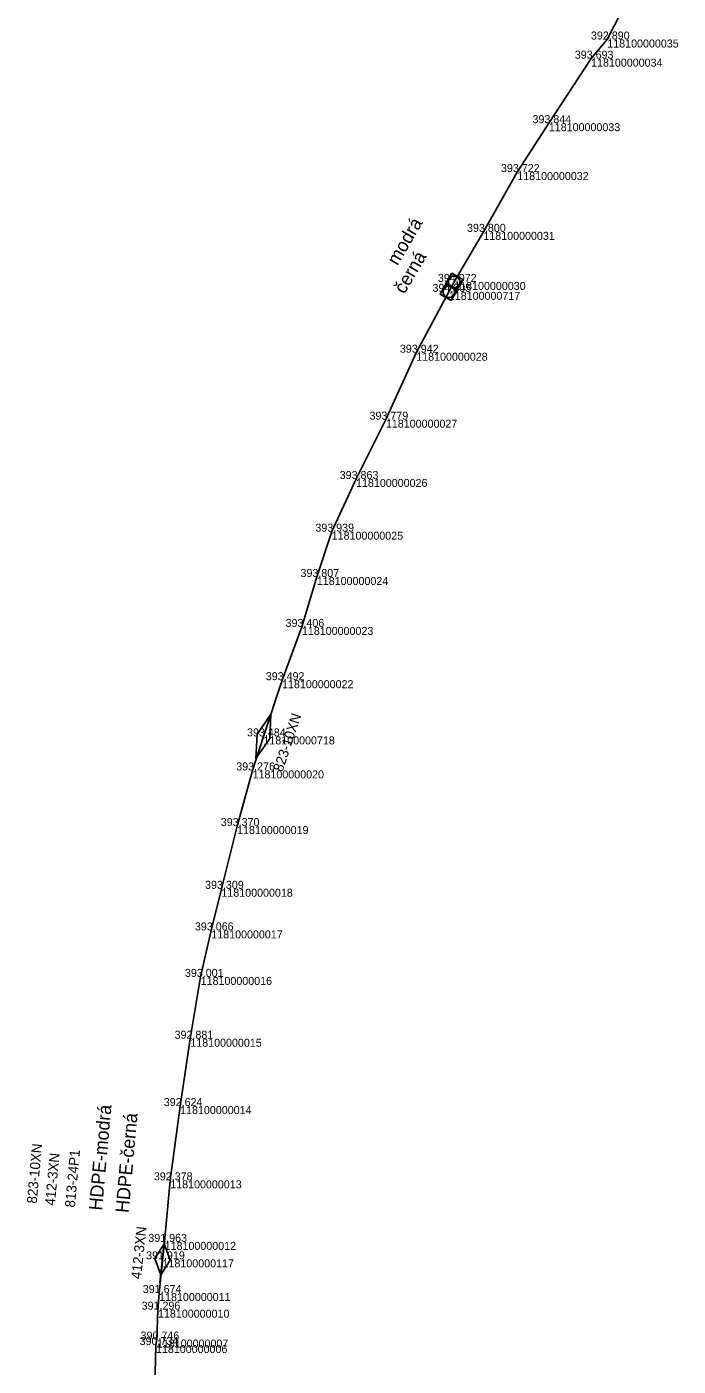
# Model space of a CAD drawing. Extents: x -724084 to -720954, y -948423 to -945131.
# Drawn here: x -721963.8 to -721866.1, y -947400.9 to -947200 of the extents above; entities that cross this region are included whole.
import ezdxf

# ---------------------------------------------------------------- set-up
doc = ezdxf.new("R2010")
doc.units = 0
for name, color, linetype in [('Vrstva 28', 7, 'Continuous'), ('Vrstva 31', 7, 'Continuous'), ('Vrstva 33', 7, 'Continuous'), ('Vrstva 60', 7, 'Continuous'), ('Vrstva 61', 7, 'Continuous')]:
    doc.layers.add(name, color=color, linetype=linetype)

msp = doc.modelspace()

# ---------------------------------------------------------------- linework, layer by layer
at = {"layer": 'Vrstva 28'}
for p, q in [((-721943.82, -947388.32), (-721943.07, -947381.38)), ((-721944.6, -947384.73), (-721943.19, -947382.54)), ((-721943.19, -947382.54), (-721942.28, -947384.98)), ((-721943.69, -947387.17), (-721944.6, -947384.73)), ((-721942.28, -947384.98), (-721943.69, -947387.17))]:
    msp.add_line(p, q, dxfattribs=at)
msp.add_lwpolyline([(-721944.57, -947404.06), (-721944.42, -947397.7), (-721944.28, -947396.88), (-721944.12, -947392.4), (-721943.95, -947389.9), (-721943.12, -947382.23), (-721942.28, -947373), (-721940.8, -947361.86), (-721939.27, -947351.76), (-721937.72, -947342.48), (-721936.12, -947335.51), (-721934.61, -947329.27), (-721932.25, -947319.86), (-721929.93, -947311.51), (-721928.31, -947306.41), (-721925.51, -947297.98), (-721922.53, -947289.99), (-721920.29, -947282.5), (-721918.06, -947275.7), (-721914.41, -947267.8), (-721909.93, -947258.9), (-721905.38, -947248.86), (-721900.49, -947239.73), (-721899.68, -947238.24), (-721895.31, -947230.73), (-721890.22, -947221.76), (-721885.49, -947214.43), (-721879.15, -947204.75), (-721876.72, -947201.88), (-721874.78, -947198.06)], dxfattribs=at)
at = {"layer": 'Vrstva 31'}
for points in [[(-721944.57, -947404.06), (-721944.42, -947397.7), (-721944.28, -947396.88), (-721944.12, -947392.4), (-721943.95, -947389.9), (-721943.12, -947382.23), (-721942.28, -947373), (-721940.8, -947361.86), (-721939.27, -947351.76), (-721937.72, -947342.48), (-721936.12, -947335.51), (-721934.61, -947329.27), (-721932.25, -947319.86), (-721929.93, -947311.51), (-721928.31, -947306.41), (-721925.51, -947297.98), (-721922.53, -947289.99), (-721920.29, -947282.5), (-721918.06, -947275.7), (-721914.41, -947267.8), (-721909.93, -947258.9), (-721905.38, -947248.86), (-721900.49, -947239.73), (-721899.68, -947238.24), (-721895.31, -947230.73), (-721890.22, -947221.76), (-721885.49, -947214.43), (-721879.15, -947204.75), (-721876.72, -947201.88), (-721874.78, -947198.06)], [(-721929.42, -947309.73), (-721929.26, -947306.1), (-721927.21, -947303.09), (-721927.36, -947306.73), (-721929.42, -947309.73)]]:
    msp.add_lwpolyline(points, dxfattribs=at)
at = {"layer": 'Vrstva 33'}
msp.add_lwpolyline([(-721944.57, -947404.06), (-721944.42, -947397.7), (-721944.28, -947396.88), (-721944.12, -947392.4), (-721943.95, -947389.9), (-721943.12, -947382.23), (-721942.28, -947373), (-721940.8, -947361.86), (-721939.27, -947351.76), (-721937.72, -947342.48), (-721936.12, -947335.51), (-721934.61, -947329.27), (-721932.25, -947319.86), (-721929.93, -947311.51), (-721928.31, -947306.41), (-721925.51, -947297.98), (-721922.53, -947289.99), (-721920.29, -947282.5), (-721918.06, -947275.7), (-721914.41, -947267.8), (-721909.93, -947258.9), (-721905.38, -947248.86), (-721900.49, -947239.73), (-721899.68, -947238.24), (-721895.31, -947230.73), (-721890.22, -947221.76), (-721885.49, -947214.43), (-721879.15, -947204.75), (-721876.72, -947201.88), (-721874.78, -947198.06)], dxfattribs=at)
for points in [[(-721899.33, -947239.55), (-721898.37, -947237.89), (-721900.03, -947236.93), (-721900.99, -947238.59)], [(-721900.14, -947241.05), (-721899.18, -947239.39), (-721900.83, -947238.42), (-721901.8, -947240.08)]]:
    msp.add_lwpolyline(points, close=True, dxfattribs=at)
for centre in [(-721900.49, -947239.73), (-721899.68, -947238.24)]:
    msp.add_circle(centre, 0.864, dxfattribs=at)
at = {"layer": 'Vrstva 60'}
for p, q in [((-721876.72, -947201.88), (-721876.72, -947201.88)), ((-721879.15, -947204.75), (-721879.15, -947204.75)), ((-721885.49, -947214.43), (-721885.49, -947214.43)), ((-721890.22, -947221.76), (-721890.22, -947221.76)), ((-721895.31, -947230.73), (-721895.31, -947230.73)), ((-721899.68, -947238.24), (-721899.68, -947238.24)), ((-721900.49, -947239.73), (-721900.49, -947239.73)), ((-721905.38, -947248.86), (-721905.38, -947248.86)), ((-721909.93, -947258.9), (-721909.93, -947258.9)), ((-721914.41, -947267.8), (-721914.41, -947267.8)), ((-721918.06, -947275.7), (-721918.06, -947275.7)), ((-721920.29, -947282.5), (-721920.29, -947282.5)), ((-721922.53, -947289.99), (-721922.53, -947289.99)), ((-721925.51, -947297.98), (-721925.51, -947297.98)), ((-721928.31, -947306.41), (-721928.31, -947306.41)), ((-721929.93, -947311.51), (-721929.93, -947311.51)), ((-721932.25, -947319.86), (-721932.25, -947319.86)), ((-721934.61, -947329.27), (-721934.61, -947329.27)), ((-721936.12, -947335.51), (-721936.12, -947335.51)), ((-721937.72, -947342.48), (-721937.72, -947342.48)), ((-721939.27, -947351.76), (-721939.27, -947351.76)), ((-721940.8, -947361.86), (-721940.8, -947361.86)), ((-721942.28, -947373), (-721942.28, -947373)), ((-721943.12, -947382.23), (-721943.12, -947382.23)), ((-721943.44, -947384.85), (-721943.44, -947384.85)), ((-721943.95, -947389.9), (-721943.95, -947389.9)), ((-721944.12, -947392.4), (-721944.12, -947392.4)), ((-721944.28, -947396.88), (-721944.28, -947396.88)), ((-721944.42, -947397.7), (-721944.42, -947397.7))]:
    msp.add_line(p, q, dxfattribs=at)

# ---------------------------------------------------------------- texts
at = {"layer": 'Vrstva 28'}
for s, rotation, p in [('412-3XN', 84.8218, (-721959.59, -947376.84)), ('813-24P1', 84.8218, (-721956.6, -947377.12)), ('412-3XN', 83.8139, (-721946.68, -947387.87))]:
    msp.add_text(s, height=1.5, rotation=rotation, dxfattribs=at).set_placement(p)
at = {"layer": 'Vrstva 31'}
for rotation, p in [(71.5854, (-721925.46, -947311.83)), (84.8218, (-721962.32, -947376.54))]:
    msp.add_text('823-10XN', height=1.5, rotation=rotation, dxfattribs=at).set_placement(p)
at = {"layer": 'Vrstva 33'}
for s, rotation, p in [('modrá', 59.7849, (-721908.18, -947235.9)), ('černá', 59.7849, (-721907.14, -947240.16)), ('HDPE-modrá', 84.8218, (-721952.52, -947377.58)), ('HDPE-černá', 84.8218, (-721948.53, -947377.94))]:
    msp.add_text(s, height=2, rotation=rotation, dxfattribs=at).set_placement(p)
at = {"layer": 'Vrstva 60'}
for s, p in [('118100000035', (-721876.72, -947203.08)), ('118100000034', (-721879.15, -947205.95)), ('118100000033', (-721885.49, -947215.63)), ('118100000032', (-721890.22, -947222.96)), ('118100000031', (-721895.31, -947231.93)), ('118100000030', (-721899.68, -947239.44)), ('118100000717', (-721900.49, -947240.93)), ('118100000028', (-721905.38, -947250.06)), ('118100000027', (-721909.93, -947260.1)), ('118100000026', (-721914.41, -947268.99)), ('118100000025', (-721918.06, -947276.9)), ('118100000024', (-721920.29, -947283.7)), ('118100000023', (-721922.53, -947291.19)), ('118100000022', (-721925.51, -947299.18)), ('118100000718', (-721928.31, -947307.61)), ('118100000020', (-721929.93, -947312.71)), ('118100000019', (-721932.25, -947321.06)), ('118100000018', (-721934.61, -947330.46)), ('118100000017', (-721936.12, -947336.71)), ('118100000016', (-721937.72, -947343.68)), ('118100000015', (-721939.27, -947352.96)), ('118100000014', (-721940.8, -947363.06)), ('118100000013', (-721942.28, -947374.2)), ('118100000012', (-721943.12, -947383.43)), ('118100000117', (-721943.44, -947386.05)), ('118100000011', (-721943.95, -947391.1)), ('118100000010', (-721944.12, -947393.6)), ('118100000007', (-721944.28, -947398.08)), ('118100000006', (-721944.42, -947398.9))]:
    msp.add_text(s, height=1.2, dxfattribs=at).set_placement(p)
at = {"layer": 'Vrstva 61'}
for s, p in [('392.890', (-721879.17, -947201.88)), ('393.693', (-721881.6, -947204.75)), ('393.844', (-721887.94, -947214.43)), ('393.722', (-721892.67, -947221.76)), ('393.800', (-721897.76, -947230.73)), ('394.305', (-721902.94, -947239.73)), ('394.072', (-721902.13, -947238.24)), ('393.942', (-721907.83, -947248.86)), ('393.779', (-721912.39, -947258.9)), ('393.863', (-721916.86, -947267.8)), ('393.939', (-721920.51, -947275.7)), ('393.807', (-721922.74, -947282.5)), ('393.406', (-721924.98, -947289.99)), ('393.492', (-721927.95, -947297.98)), ('393.484', (-721930.76, -947306.41)), ('393.276', (-721932.38, -947311.51)), ('393.370', (-721934.7, -947319.86)), ('393.309', (-721937.06, -947329.27)), ('393.066', (-721938.58, -947335.51)), ('393.001', (-721940.08, -947342.48)), ('392.881', (-721941.63, -947351.76)), ('392.624', (-721943.25, -947361.86)), ('392.378', (-721944.74, -947373)), ('391.963', (-721945.57, -947382.23)), ('391.919', (-721945.9, -947384.85)), ('391.674', (-721946.4, -947389.9)), ('391.296', (-721946.57, -947392.4)), ('390.734', (-721946.87, -947397.7)), ('390.746', (-721946.73, -947396.88))]:
    msp.add_text(s, height=1.2, dxfattribs=at).set_placement(p)

doc.saveas('drawing.dxf')
